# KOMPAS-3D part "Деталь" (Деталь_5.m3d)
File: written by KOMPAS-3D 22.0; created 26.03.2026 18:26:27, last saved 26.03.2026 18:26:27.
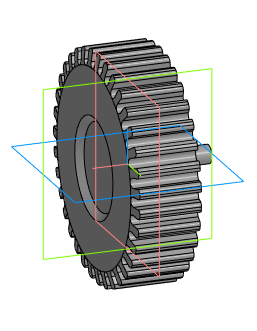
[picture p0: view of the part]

Document properties: Автор: Пользователь Windows; Полное имя файла: F:\Танк\Деталь_5.m3d

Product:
- Part/product: Деталь

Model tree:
1. Операция без истории:1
